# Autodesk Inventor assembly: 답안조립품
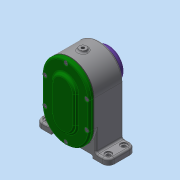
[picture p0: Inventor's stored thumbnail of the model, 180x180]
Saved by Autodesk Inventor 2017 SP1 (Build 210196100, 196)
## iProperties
Part Number: 답안조립품
Material: 일반
Document SubType Name: Assembly
Designer: MRC
Author: MRC
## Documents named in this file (19)
- C:\Users\MRC\Desktop\710609V1006\답안조립품.iam
- C:\Users\MRC\Desktop\710609V1006\본체.ipt
- C:\Users\MRC\Desktop\710609V1006\개스킷 A.ipt
- C:\Users\MRC\Desktop\710609V1006\개스킷 B.ipt
- C:\Users\MRC\Desktop\710609V1006\베어링 6001.ipt
- 베어링 6001.ipt
- C:\Users\MRC\Desktop\710609V1006\베어링 6002.ipt
- 베어링 6002.ipt
- C:\Users\MRC\Desktop\710609V1006\볼트 M4.ipt
- C:\Users\MRC\Desktop\710609V1006\스퍼기어 A.ipt
- C:\Users\MRC\Desktop\710609V1006\스퍼기어 B.ipt
- C:\Users\MRC\Desktop\710609V1006\오일 실 12 22 7.ipt
- C:\Users\MRC\Desktop\710609V1006\축 A.ipt
- C:\Users\MRC\Desktop\710609V1006\축 B.ipt
- C:\Users\MRC\Desktop\710609V1006\칼라.ipt
- C:\Users\MRC\Desktop\710609V1006\커버 A.ipt
- C:\Users\MRC\Desktop\710609V1006\커버 B.ipt
- C:\Users\MRC\Desktop\710609V1006\키 4 x 4 x 12.ipt
- C:\Users\MRC\Desktop\710609V1006\키 5 x 5 x 12.ipt
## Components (2 placed, 2 different names)
1. 개스킷 A:1
2. 개스킷 B:1
